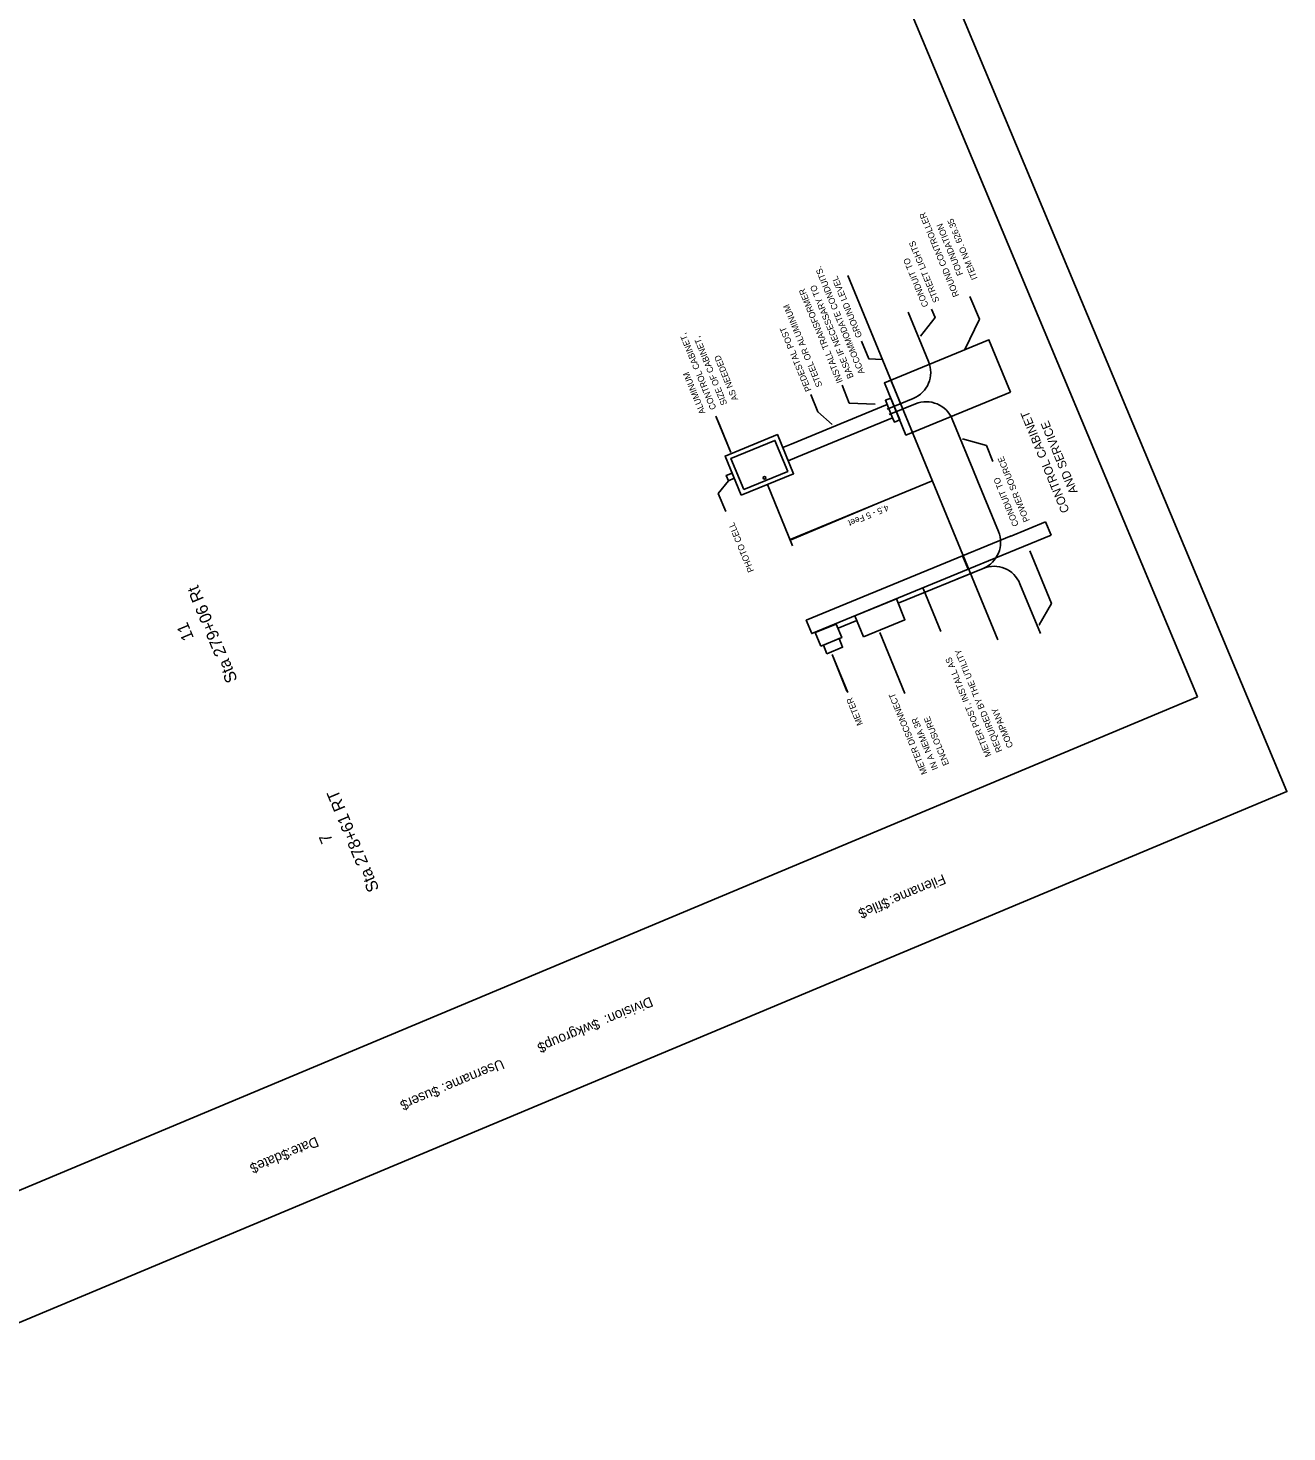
# Model space of a CAD drawing. Extents: x 1111244 to 1112080, y 617020 to 618016.
# Drawn here: x 1111662.3 to 1112080, y 617019.6 to 617485.3 of the extents above; entities that cross this region are included whole.
import ezdxf

# ---------------------------------------------------------------- set-up
doc = ezdxf.new("R2010")
doc.units = 0
for name, color, linetype in [('BORDER', 7, 'Continuous'), ('D_Lighting_Text', 7, 'Continuous'), ('Default', 7, 'Continuous'), ('Liting Text', 7, 'Continuous'), ('PLOT BOUNDARY', 7, 'Continuous')]:
    doc.layers.add(name, color=color, linetype=linetype)

msp = doc.modelspace()

# ---------------------------------------------------------------- linework, layer by layer
at = {"layer": 'BORDER'}
for p, q in [((1112050.29, 617263.43), (1111741.35, 618001.37)), ((1111566.01, 617060.69), (1112050.29, 617263.43))]:
    msp.add_line(p, q, dxfattribs=at)
at = {"layer": 'D_Lighting_Text'}
for p, q in [((1111977.97, 617388.67), (1111973.1, 617378.67)), ((1111934.78, 617360.9), (1111943.35, 617360.54)), ((1111924.37, 617357.93), (1111929.06, 617353.74)), ((1111891.3, 617330.9), (1111894.66, 617335.12)), ((1111944.38, 617327.67), (1111962.04, 617334.94)), ((1111944.38, 617327.67), (1111915.2, 617315.46)), ((1111965.15, 617285.08), (1111959.27, 617299.37)), ((1112001.85, 617294.45), (1111997.8, 617287.31)), ((1111953.2, 617264.58), (1111944.9, 617284.74)), ((1111933.97, 617265.31), (1111929.14, 617277.49))]:
    msp.add_line(p, q, dxfattribs=at)
for points in [[(1111962.11, 617392.07), (1111963.27, 617389.26), (1111958.38, 617383.11)], [(1111890.53, 617356.54), (1111891.82, 617353.46), (1111895.51, 617344.44)], [(1111982.47, 617341.55), (1111980.31, 617346.79), (1111972.41, 617349.02)]]:
    msp.add_lwpolyline(points, dxfattribs=at)
at = {"layer": 'Default'}
msp.add_lwpolyline([(1111572.69, 617019.61), (1111244.44, 617803.67), (1111751.77, 618016.07), (1112080.02, 617232.01)], close=True, dxfattribs=at)
at = {"layer": 'Liting Text'}
for p, q in [((1111984.05, 617282.4), (1111934.35, 617403.16)), ((1111961.1, 617374.63), (1111954.35, 617391.05)), ((1111947.33, 617358.83), (1111956, 617362.39)), ((1111948.07, 617357.04), (1111956.74, 617360.61)), ((1111890.53, 617356.54), (1111895.51, 617344.44)), ((1111968.97, 617355.51), (1111975.79, 617338.96)), ((1111977.48, 617334.84), (1111975.79, 617338.96)), ((1111891.3, 617330.9), (1111894.66, 617335.12)), ((1111907.61, 617333.86), (1111915.96, 617313.58)), ((1111944.38, 617327.67), (1111962.04, 617334.94)), ((1111984.29, 617318.29), (1111977.48, 617334.84)), ((1111984.29, 617318.29), (1111977.48, 617334.84)), ((1111891.3, 617330.9), (1111893.77, 617324.89)), ((1111944.38, 617327.67), (1111915.19, 617315.66)), ((1111988.12, 617316.59), (1111999.94, 617321.46)), ((1112001.74, 617317.07), (1111999.94, 617321.46)), ((1111974.24, 617305.75), (1112001.74, 617317.07)), ((1111951.02, 617294.46), (1111979.19, 617306.05)), ((1111951.02, 617294.46), (1111979.19, 617306.05)), ((1111970.52, 617302.48), (1111979.19, 617306.05)), ((1111965.15, 617285.08), (1111959.27, 617299.37)), ((1111991.43, 617300.95), (1111998.24, 617284.4)), ((1111937.31, 617288.81), (1111931.05, 617286.24)), ((1111953.2, 617264.58), (1111944.9, 617284.74)), ((1111934.33, 617264.87), (1111929.14, 617277.49))]:
    msp.add_line(p, q, dxfattribs=at)
for points in [[(1111974.84, 617396.26), (1111977.97, 617388.67), (1111973.1, 617378.67)], [(1111962.11, 617392.07), (1111963.27, 617389.26), (1111958.38, 617383.11)], [(1111938.87, 617381.41), (1111941.26, 617375.6), (1111945.71, 617375.38)], [(1111932.37, 617366.77), (1111934.78, 617360.9), (1111943.35, 617360.54)], [(1111946.45, 617367.59), (1111948.62, 617368.48), (1111955.76, 617351.14)], [(1111917.34, 617342.94), (1111949.18, 617356.04), (1111947.39, 617360.37), (1111915.52, 617347.25)], [(1111921.98, 617363.74), (1111924.37, 617357.93), (1111929.06, 617353.74)], [(1111948.29, 617358.21), (1111946.8, 617361.82), (1111948.53, 617362.53), (1111951.51, 617355.31), (1111949.77, 617354.6), (1111949.18, 617356.04)], [(1111915.52, 617347.25), (1111912.71, 617346.1), (1111914.5, 617341.77), (1111917.34, 617342.94)], [(1111982.47, 617341.55), (1111980.31, 617346.79), (1111972.41, 617349.02), (1111972.41, 617349.02)], [(1111972.41, 617310.2), (1111988.52, 617316.83), (1111988.55, 617316.77)], [(1111933.63, 617289.09), (1111974.23, 617305.8), (1111972.41, 617310.2), (1111931.78, 617293.47)], [(1111994.7, 617311.83), (1112001.85, 617294.45), (1111997.8, 617287.31), (1111997.8, 617287.31)], [(1111931.78, 617293.47), (1111920.52, 617288.84), (1111922.34, 617284.44), (1111933.63, 617289.09)], [(1111927.38, 617277.74), (1111932.58, 617279.88), (1111931.41, 617282.74), (1111926.2, 617280.6), (1111927.38, 617277.74)]]:
    msp.add_lwpolyline(points, dxfattribs=at)
for points in [[(1111988.27, 617364.52), (1111953.59, 617350.25), (1111946.45, 617367.59), (1111981.13, 617381.86)], [(1111898.94, 617330.3), (1111893.59, 617343.3), (1111910.93, 617350.44), (1111916.28, 617337.43)], [(1111899.74, 617332.21), (1111895.5, 617342.5), (1111910.13, 617348.52), (1111914.37, 617338.23)], [(1111894.66, 617335.12), (1111893.95, 617336.86), (1111895.91, 617337.67), (1111896.62, 617335.93)], [(1111896.27, 617336.8), (1111895.62, 617338.37), (1111895.62, 617338.37), (1111896.27, 617336.8)], [(1111939.53, 617283.35), (1111936.68, 617290.29), (1111950.41, 617295.94), (1111953.26, 617289)], [(1111925.34, 617280.25), (1111923.49, 617284.73), (1111930.43, 617287.59), (1111932.27, 617283.1)]]:
    msp.add_lwpolyline(points, close=True, dxfattribs=at)
msp.add_circle((1111906.64, 617336.08), 0.416, dxfattribs=at)
for centre, start, end in [((1111952.43, 617371.06), 292.37, 22.37), ((1111960.3, 617351.94), 22.37, 112.37), ((1111975.62, 617314.72), 292.37, 22.37), ((1111975.62, 617314.72), 292.37, 22.37), ((1111982.76, 617297.38), 22.37, 112.37)]:
    msp.add_arc(centre, 9.38, start, end, dxfattribs=at)
at = {"layer": 'PLOT BOUNDARY'}
msp.add_lwpolyline([(1112080.02, 617232.01), (1111751.77, 618016.07), (1111244.44, 617803.67), (1111572.69, 617019.61)], close=True, dxfattribs=at)

# ---------------------------------------------------------------- texts
at = {"layer": 'BORDER'}
for s, p in [('Filename:', (1111965.92, 617204.72)), ('$file$', (1111947.35, 617196.94)), ('Division:', (1111868.75, 617164.04)), ('$wkgroup$', (1111851.21, 617156.7)), ('Username:', (1111819.4, 617143.38)), ('$user$', (1111798.07, 617134.45)), ('$date$', (1111748.2, 617113.57)), ('Date:', (1111757.83, 617117.6))]:
    msp.add_text(s, height=3.348, rotation=202.7167, dxfattribs=at).set_placement(p)
at = {"layer": 'D_Lighting_Text'}
for s, p in [('Sta 279+06 Rt', (1111731.88, 617269.06)), ('11', (1111717.36, 617283.02)), ('Sta 278+61 RT', (1111778.88, 617199.68)), ('7', (1111763.46, 617215.79))]:
    msp.add_text(s, height=4, rotation=112.7167, dxfattribs=at).set_placement(p)
at = {"layer": 'Liting Text'}
for s, height, rotation, p in [('ROUND CONTROLLER ', 2.0835, 112.37, (1111971.3, 617396.58)), ('FOUNDATION', 2.083, 112.37, (1111972.61, 617403.66)), ('ITEM NO. 626.35', 2.0835, 112.37, (1111977.41, 617402.26)), ('STREET LIGHTS', 2.0835, 112.37, (1111964.74, 617394.72)), ('CONDUIT TO', 2.083, 112.37, (1111961.13, 617393.23)), ('ACCOMMODATE CONDUITS.', 2.0835, 112.37, (1111939.9, 617370.99)), ('GROUND LEVEL', 2.0835, 112.37, (1111939.1, 617383.06)), ('INSTALL TRANSFORMER', 2.0835, 112.37, (1111932.68, 617368.02)), ('BASE IF NECESSARY TO', 2.0835, 112.37, (1111936.29, 617369.51)), ('STEEL OR ALUMINUM', 2.0835, 112.37, (1111925.89, 617366.68)), ('CONTROL CABINET,', 2.0835, 112.37, (1111890.72, 617359.17)), ('SIZE OF CABINET, ', 2.0835, 112.37, (1111894.33, 617360.65)), ('PEDESTAL POST', 2.0835, 112.37, (1111922.28, 617365.2)), ('AS NEEDED', 2.083, 112.37, (1111897.94, 617362.14)), ('ALUMINUM', 2.083, 112.37, (1111887.1, 617357.68)), ('CONTROL CABINET', 2.8431, 112.37, (1112007.92, 617325.14)), ('AND SERVICE', 2.8431, 112.37, (1112010.65, 617331.44)), ('POWER SOURCE', 2.0835, 112.37, (1111994.7, 617321.94)), ('CONDUIT TO', 2.083, 112.37, (1111991.08, 617320.45)), ('4.5 - 5 Feet', 2.0835, 202.37, (1111947.38, 617327.25)), ('PHOTO CELL', 2.083, 112.37, (1111903.21, 617305.25)), ('METER POST, INSTALL AS', 2.0835, 112.37, (1111982, 617244.02)), ('REQUIRED BY THE UTILITY', 2.0835, 112.37, (1111985.61, 617245.51)), ('METER ', 2.083, 112.37, (1111939.38, 617254.42)), ('METER DISCONNECT', 2.0835, 112.37, (1111960.75, 617238.15)), ('COMPANY', 2.083, 112.37, (1111989.23, 617247)), ('IN A NEMA 3R', 2.0835, 112.37, (1111964.36, 617239.64)), ('ENCLOSURE', 2.083, 112.37, (1111967.97, 617241.13))]:
    msp.add_text(s, height=height, rotation=rotation, dxfattribs=at).set_placement(p)

doc.saveas('drawing.dxf')
